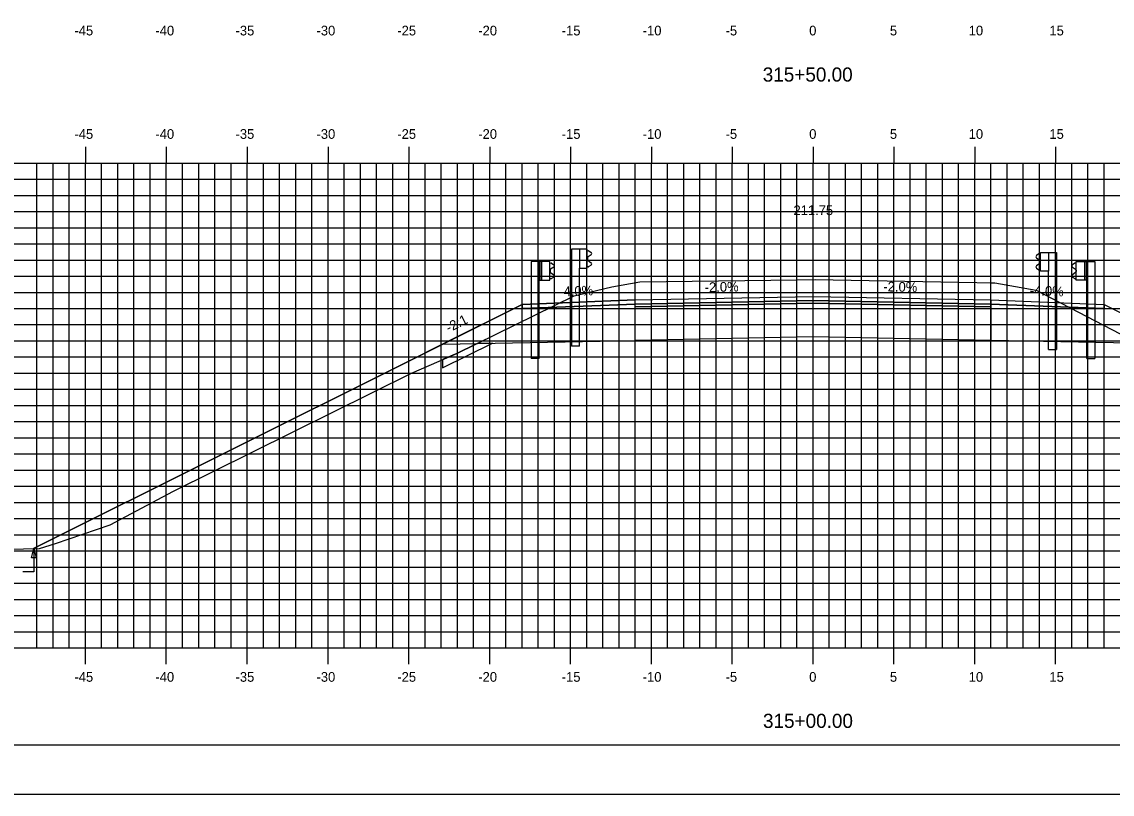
# Model space of a CAD drawing. Extents: x 1138541 to 1138711, y 608981 to 609091.
# Drawn here: x 1138575.5 to 1138642.9, y 608981.3 to 609029.1 of the extents above; entities that cross this region are included whole.
import ezdxf

# ---------------------------------------------------------------- set-up
doc = ezdxf.new("R2010")
doc.units = 0
for name, color, linetype in [('ANNOTATION', 7, 'Continuous'), ('BORDER', 7, 'Continuous'), ('D_Guardrail_Beam_Lt', 7, 'Continuous'), ('D_Guardrail_Beam_Rt', 7, 'Continuous'), ('D_Roadway_Centerline', 7, 'Continuous'), ('D_Roadway_Centerline_Text', 7, 'Continuous'), ('D_Roadway_Edge_Shoulder', 7, 'Continuous'), ('D_Roadway_Edge_TW', 7, 'Continuous'), ('D_Roadway_Pavement', 7, 'Continuous'), ('D_Roadway_SlopeLines', 7, 'Continuous'), ('D_Roadway_SubGrade', 7, 'Continuous'), ('D_Text_Standard', 7, 'Continuous'), ('H_V ANNOTATION', 7, 'Continuous'), ('MAJOR', 7, 'Continuous'), ('MINOR', 7, 'Continuous'), ('PLOT BOUNDARY', 7, 'Continuous'), ('S_Guardrail_Beam', 7, 'Continuous'), ('S_Roadway_Centerline', 7, 'Continuous'), ('SHADING', 7, 'Continuous')]:
    doc.layers.add(name, color=color, linetype=linetype)

msp = doc.modelspace()

# ---------------------------------------------------------------- linework, layer by layer
msp.add_lwpolyline([(1138576.228, 608996.48), (1138599.518, 609008.124), (1138601.518, 609009.124), (1138606.435, 609011.583), (1138606.436, 609011.583), (1138613.436, 609011.863), (1138624.436, 609012.083), (1138635.436, 609011.863), (1138642.436, 609011.583), (1138647.352, 609009.124), (1138649.352, 609008.124), (1138671.518, 608997.041)])
at = {"layer": 'BORDER'}
msp.add_lwpolyline([(1138549.436, 608984.335), (1138709.436, 608984.335), (1138709.436, 609089.335), (1138549.436, 609089.335)], close=True, dxfattribs=at)
at = {"layer": 'D_Guardrail_Beam_Lt'}
for p, q in [((1138607.006, 609014.246), (1138607.006, 609008.246)), ((1138607.477, 609014.246), (1138607.006, 609014.246)), ((1138608.165, 609014.246), (1138607.477, 609014.246)), ((1138607.477, 609014.246), (1138607.477, 609013.079)), ((1138607.54, 609014.246), (1138607.54, 609013.079)), ((1138607.644, 609014.246), (1138607.644, 609013.079)), ((1138608.165, 609013.079), (1138608.165, 609014.246)), ((1138608.165, 609014.163), (1138608.239, 609014.148)), ((1138608.398, 609013.898), (1138608.203, 609013.762)), ((1138608.255, 609014.141), (1138608.398, 609014.041)), ((1138640.616, 609014.141), (1138640.473, 609014.041)), ((1138640.473, 609013.898), (1138640.668, 609013.762)), ((1138640.706, 609014.163), (1138640.632, 609014.148)), ((1138607.477, 609013.079), (1138608.165, 609013.079)), ((1138607.498, 609008.246), (1138607.498, 609013.079)), ((1138608.239, 609013.177), (1138608.165, 609013.163)), ((1138608.169, 609013.698), (1138608.169, 609013.628)), ((1138608.203, 609013.563), (1138608.398, 609013.427)), ((1138608.398, 609013.284), (1138608.255, 609013.184)), ((1138640.668, 609013.563), (1138640.473, 609013.427)), ((1138640.473, 609013.284), (1138640.616, 609013.184)), ((1138640.632, 609013.177), (1138640.706, 609013.163)), ((1138640.702, 609013.698), (1138640.702, 609013.628)), ((1138607.498, 609008.246), (1138607.006, 609008.246))]:
    msp.add_line(p, q, dxfattribs=at)
for centre, major_axis, start_param, end_param in [((1138608.248, 609013.698), (-0.0789, 0), 5.323254, 6.283185), ((1138608.231, 609014.107), (0.0417, 0), 0.959931, 1.376053), ((1138608.348, 609013.97), (0.0877, 0), 5.323254, 7.243116), ((1138640.523, 609013.97), (-0.0877, 0), 5.323254, 7.243116), ((1138640.64, 609014.107), (-0.0417, 0), 4.907132, 5.323254), ((1138640.623, 609013.698), (0.0789, 0), 0, 0.959931), ((1138608.248, 609013.628), (-0.0789, 0), 6.283185, 7.243116), ((1138608.231, 609013.218), (0.0417, 0), 4.907132, 5.323254), ((1138608.348, 609013.356), (0.0877, 0), 5.323254, 7.243116), ((1138640.523, 609013.356), (-0.0877, 0), 5.323254, 7.243116), ((1138640.64, 609013.218), (-0.0417, 0), 0.959931, 1.376053), ((1138640.623, 609013.628), (0.0789, 0), 5.323254, 6.283185)]:
    msp.add_ellipse(centre, major_axis=major_axis, ratio=0.995501, start_param=start_param, end_param=end_param, dxfattribs=at)
at = {"layer": 'D_Guardrail_Beam_Rt'}
for p, q in [((1138640.706, 609014.246), (1138641.394, 609014.246)), ((1138640.706, 609013.079), (1138640.706, 609014.246)), ((1138641.227, 609014.246), (1138641.227, 609013.079)), ((1138641.331, 609014.246), (1138641.331, 609013.079)), ((1138641.394, 609014.246), (1138641.865, 609014.246)), ((1138641.394, 609014.246), (1138641.394, 609013.079)), ((1138641.865, 609014.246), (1138641.865, 609008.246)), ((1138641.394, 609013.079), (1138640.706, 609013.079)), ((1138641.373, 609008.246), (1138641.373, 609013.079)), ((1138641.373, 609008.246), (1138641.865, 609008.246))]:
    msp.add_line(p, q, dxfattribs=at)
at = {"layer": 'D_Roadway_Edge_Shoulder'}
for points in [[(1138613.436, 609011.863), (1138606.436, 609011.583), (1138606.436, 609011.333), (1138613.436, 609011.613)], [(1138635.436, 609011.863), (1138642.436, 609011.583), (1138642.436, 609011.333), (1138635.436, 609011.613)]]:
    msp.add_lwpolyline(points, close=True, dxfattribs=at)
at = {"layer": 'D_Roadway_Edge_TW'}
msp.add_lwpolyline([(1138613.436, 609011.613), (1138613.436, 609011.863), (1138624.436, 609012.083), (1138635.436, 609011.863), (1138635.436, 609011.613), (1138624.436, 609011.833)], close=True, dxfattribs=at)
at = {"layer": 'D_Roadway_Pavement'}
msp.add_lwpolyline([(1138613.436, 609011.446), (1138613.436, 609011.613), (1138624.436, 609011.833), (1138635.436, 609011.613), (1138635.436, 609011.446), (1138624.436, 609011.666)], close=True, dxfattribs=at)
at = {"layer": 'D_Roadway_SlopeLines'}
for points in [[(1138605.065, 609009.862), (1138605.065, 609009.862)], [(1138601.518, 609009.124), (1138599.518, 609008.124)], [(1138601.518, 609008.17), (1138601.518, 609007.67), (1138604.603, 609009.186)], [(1138599.518, 609008.124), (1138576.228, 608996.48)]]:
    msp.add_lwpolyline(points, dxfattribs=at)
at = {"layer": 'D_Roadway_SubGrade'}
msp.add_lwpolyline([(1138606.436, 609011.581), (1138604.436, 609010.581), (1138576.233, 608996.48)], dxfattribs=at)
for points in [[(1138613.436, 609011.446), (1138613.436, 609011.613), (1138606.436, 609011.333), (1138606.436, 609011.583), (1138606.435, 609011.583), (1138601.518, 609009.124), (1138613.436, 609009.363)], [(1138613.436, 609009.363), (1138613.436, 609011.446), (1138624.436, 609011.666), (1138635.436, 609011.446), (1138635.436, 609009.363), (1138624.436, 609009.583)], [(1138635.436, 609011.446), (1138635.436, 609011.613), (1138642.436, 609011.333), (1138642.436, 609011.583), (1138642.436, 609011.583), (1138647.352, 609009.124), (1138635.436, 609009.363)]]:
    msp.add_lwpolyline(points, close=True, dxfattribs=at)
at = {"layer": 'D_Text_Standard'}
msp.add_lwpolyline([(1138576.233, 608996.48), (1138576.239, 608995.034), (1138575.559, 608995.034)], dxfattribs=at)
msp.add_lwpolyline([(1138576.233, 608996.48), (1138576.381, 608995.898), (1138576.09, 608995.897)], close=True, dxfattribs=at)
at = {"layer": 'MAJOR'}
for p, q in [((1138579.436, 609021.337), (1138579.436, 609020.335)), ((1138584.436, 609021.337), (1138584.436, 609020.335)), ((1138589.436, 609021.337), (1138589.436, 609020.335)), ((1138594.436, 609021.337), (1138594.436, 609020.335)), ((1138599.436, 609021.337), (1138599.436, 609020.335)), ((1138604.436, 609021.337), (1138604.436, 609020.335)), ((1138609.436, 609021.337), (1138609.436, 609020.335)), ((1138614.436, 609021.337), (1138614.436, 609020.335)), ((1138619.436, 609021.337), (1138619.436, 609020.335)), ((1138624.436, 609021.337), (1138624.436, 609020.335)), ((1138629.436, 609021.337), (1138629.436, 609020.335)), ((1138634.436, 609021.337), (1138634.436, 609020.335)), ((1138639.436, 609021.337), (1138639.436, 609020.335)), ((1138554.436, 609020.335), (1138694.436, 609020.335)), ((1138554.436, 609020.335), (1138694.436, 609020.335)), ((1138579.436, 608990.335), (1138579.436, 609020.335)), ((1138584.436, 608990.335), (1138584.436, 609020.335)), ((1138589.436, 608990.335), (1138589.436, 609020.335)), ((1138594.436, 608990.335), (1138594.436, 609020.335)), ((1138599.436, 608990.335), (1138599.436, 609020.335)), ((1138604.436, 608990.335), (1138604.436, 609020.335)), ((1138609.436, 608990.335), (1138609.436, 609020.335)), ((1138614.436, 608990.335), (1138614.436, 609020.335)), ((1138619.436, 608990.335), (1138619.436, 609020.335)), ((1138624.436, 608990.335), (1138624.436, 609020.335)), ((1138629.436, 608990.335), (1138629.436, 609020.335)), ((1138634.436, 608990.335), (1138634.436, 609020.335)), ((1138639.436, 608990.335), (1138639.436, 609020.335)), ((1138554.436, 609015.335), (1138694.436, 609015.335)), ((1138554.436, 609010.335), (1138694.436, 609010.335)), ((1138554.436, 609005.335), (1138694.436, 609005.335)), ((1138554.436, 609000.335), (1138694.436, 609000.335)), ((1138554.436, 608995.335), (1138694.436, 608995.335)), ((1138554.436, 608990.335), (1138694.436, 608990.335)), ((1138554.436, 608990.335), (1138694.436, 608990.335)), ((1138579.436, 608989.333), (1138579.436, 608990.335)), ((1138584.436, 608989.333), (1138584.436, 608990.335)), ((1138589.436, 608989.333), (1138589.436, 608990.335)), ((1138594.436, 608989.333), (1138594.436, 608990.335)), ((1138599.436, 608989.333), (1138599.436, 608990.335)), ((1138604.436, 608989.333), (1138604.436, 608990.335)), ((1138609.436, 608989.333), (1138609.436, 608990.335)), ((1138614.436, 608989.333), (1138614.436, 608990.335)), ((1138619.436, 608989.333), (1138619.436, 608990.335)), ((1138624.436, 608989.333), (1138624.436, 608990.335)), ((1138629.436, 608989.333), (1138629.436, 608990.335)), ((1138634.436, 608989.333), (1138634.436, 608990.335)), ((1138639.436, 608989.333), (1138639.436, 608990.335))]:
    msp.add_line(p, q, dxfattribs=at)
at = {"layer": 'MINOR'}
for p, q in [((1138576.436, 608990.335), (1138576.436, 609020.335)), ((1138577.436, 608990.335), (1138577.436, 609020.335)), ((1138578.436, 608990.335), (1138578.436, 609020.335)), ((1138580.436, 608990.335), (1138580.436, 609020.335)), ((1138581.436, 608990.335), (1138581.436, 609020.335)), ((1138582.436, 608990.335), (1138582.436, 609020.335)), ((1138583.436, 608990.335), (1138583.436, 609020.335)), ((1138585.436, 608990.335), (1138585.436, 609020.335)), ((1138586.436, 608990.335), (1138586.436, 609020.335)), ((1138587.436, 608990.335), (1138587.436, 609020.335)), ((1138588.436, 608990.335), (1138588.436, 609020.335)), ((1138590.436, 608990.335), (1138590.436, 609020.335)), ((1138591.436, 608990.335), (1138591.436, 609020.335)), ((1138592.436, 608990.335), (1138592.436, 609020.335)), ((1138593.436, 608990.335), (1138593.436, 609020.335)), ((1138595.436, 608990.335), (1138595.436, 609020.335)), ((1138596.436, 608990.335), (1138596.436, 609020.335)), ((1138597.436, 608990.335), (1138597.436, 609020.335)), ((1138598.436, 608990.335), (1138598.436, 609020.335)), ((1138600.436, 608990.335), (1138600.436, 609020.335)), ((1138601.436, 608990.335), (1138601.436, 609020.335)), ((1138602.436, 608990.335), (1138602.436, 609020.335)), ((1138603.436, 608990.335), (1138603.436, 609020.335)), ((1138605.436, 608990.335), (1138605.436, 609020.335)), ((1138606.436, 608990.335), (1138606.436, 609020.335)), ((1138607.436, 608990.335), (1138607.436, 609020.335)), ((1138608.436, 608990.335), (1138608.436, 609020.335)), ((1138610.436, 608990.335), (1138610.436, 609020.335)), ((1138611.436, 608990.335), (1138611.436, 609020.335)), ((1138612.436, 608990.335), (1138612.436, 609020.335)), ((1138613.436, 608990.335), (1138613.436, 609020.335)), ((1138615.436, 608990.335), (1138615.436, 609020.335)), ((1138616.436, 608990.335), (1138616.436, 609020.335)), ((1138617.436, 608990.335), (1138617.436, 609020.335)), ((1138618.436, 608990.335), (1138618.436, 609020.335)), ((1138620.436, 608990.335), (1138620.436, 609020.335)), ((1138621.436, 608990.335), (1138621.436, 609020.335)), ((1138622.436, 608990.335), (1138622.436, 609020.335)), ((1138623.436, 608990.335), (1138623.436, 609020.335)), ((1138625.436, 608990.335), (1138625.436, 609020.335)), ((1138626.436, 608990.335), (1138626.436, 609020.335)), ((1138627.436, 608990.335), (1138627.436, 609020.335)), ((1138628.436, 608990.335), (1138628.436, 609020.335)), ((1138630.436, 608990.335), (1138630.436, 609020.335)), ((1138631.436, 608990.335), (1138631.436, 609020.335)), ((1138632.436, 608990.335), (1138632.436, 609020.335)), ((1138633.436, 608990.335), (1138633.436, 609020.335)), ((1138635.436, 608990.335), (1138635.436, 609020.335)), ((1138636.436, 608990.335), (1138636.436, 609020.335)), ((1138637.436, 608990.335), (1138637.436, 609020.335)), ((1138638.436, 608990.335), (1138638.436, 609020.335)), ((1138640.436, 608990.335), (1138640.436, 609020.335)), ((1138641.436, 608990.335), (1138641.436, 609020.335)), ((1138642.436, 608990.335), (1138642.436, 609020.335)), ((1138554.436, 609019.335), (1138694.436, 609019.335)), ((1138554.436, 609018.335), (1138694.436, 609018.335)), ((1138554.436, 609017.335), (1138694.436, 609017.335)), ((1138554.436, 609016.335), (1138694.436, 609016.335)), ((1138554.436, 609014.335), (1138694.436, 609014.335)), ((1138554.436, 609013.335), (1138694.436, 609013.335)), ((1138554.436, 609012.335), (1138694.436, 609012.335)), ((1138554.436, 609011.335), (1138694.436, 609011.335)), ((1138554.436, 609009.335), (1138694.436, 609009.335)), ((1138554.436, 609008.335), (1138694.436, 609008.335)), ((1138554.436, 609007.335), (1138694.436, 609007.335)), ((1138554.436, 609006.335), (1138694.436, 609006.335)), ((1138554.436, 609004.335), (1138694.436, 609004.335)), ((1138554.436, 609003.335), (1138694.436, 609003.335)), ((1138554.436, 609002.335), (1138694.436, 609002.335)), ((1138554.436, 609001.335), (1138694.436, 609001.335)), ((1138554.436, 608999.335), (1138694.436, 608999.335)), ((1138554.436, 608998.335), (1138694.436, 608998.335)), ((1138554.436, 608997.335), (1138694.436, 608997.335)), ((1138554.436, 608996.335), (1138694.436, 608996.335)), ((1138554.436, 608994.335), (1138694.436, 608994.335)), ((1138554.436, 608993.335), (1138694.436, 608993.335)), ((1138554.436, 608992.335), (1138694.436, 608992.335)), ((1138554.436, 608991.335), (1138694.436, 608991.335))]:
    msp.add_line(p, q, dxfattribs=at)
at = {"layer": 'PLOT BOUNDARY'}
msp.add_lwpolyline([(1138541.342, 608981.276), (1138711.342, 608981.276), (1138711.342, 609091.276), (1138541.342, 609091.276)], close=True, dxfattribs=at)
at = {"layer": 'S_Guardrail_Beam'}
for p, q in [((1138609.489, 609014.999), (1138609.489, 609008.999)), ((1138609.98, 609014.999), (1138609.489, 609014.999)), ((1138610.47, 609014.999), (1138609.98, 609014.999)), ((1138609.98, 609014.999), (1138609.98, 609013.833)), ((1138610.47, 609013.833), (1138610.47, 609014.999)), ((1138610.47, 609014.926), (1138610.552, 609014.912)), ((1138610.483, 609014.462), (1138610.483, 609014.371)), ((1138610.712, 609014.662), (1138610.517, 609014.526)), ((1138610.569, 609014.905), (1138610.712, 609014.805)), ((1138638.401, 609014.711), (1138638.258, 609014.611)), ((1138638.258, 609014.468), (1138638.453, 609014.332)), ((1138638.5, 609014.732), (1138638.418, 609014.718)), ((1138638.5, 609014.805), (1138638.99, 609014.805)), ((1138638.5, 609013.639), (1138638.5, 609014.805)), ((1138638.99, 609014.805), (1138639.481, 609014.805)), ((1138638.99, 609014.805), (1138638.99, 609013.639)), ((1138639.481, 609014.805), (1138639.481, 609008.805)), ((1138609.98, 609008.999), (1138609.98, 609013.833)), ((1138609.98, 609013.833), (1138610.47, 609013.833)), ((1138610.552, 609013.92), (1138610.47, 609013.906)), ((1138610.517, 609014.306), (1138610.712, 609014.17)), ((1138610.712, 609014.027), (1138610.569, 609013.927)), ((1138638.453, 609014.112), (1138638.258, 609013.976)), ((1138638.258, 609013.833), (1138638.401, 609013.733)), ((1138638.487, 609014.267), (1138638.487, 609014.176)), ((1138638.418, 609013.726), (1138638.5, 609013.711)), ((1138638.99, 609013.639), (1138638.5, 609013.639)), ((1138638.99, 609008.805), (1138638.99, 609013.639)), ((1138609.98, 609008.999), (1138609.489, 609008.999)), ((1138638.99, 609008.805), (1138639.481, 609008.805))]:
    msp.add_line(p, q, dxfattribs=at)
for centre, major_axis, start_param, end_param in [((1138610.562, 609014.462), (-0.0789, 0), 5.323254, 6.283185), ((1138610.545, 609014.871), (0.0417, 0), 0.959931, 1.396263), ((1138610.662, 609014.734), (0.0877, 0), 5.323254, 7.243116), ((1138638.308, 609014.539), (-0.0877, 0), 5.323254, 7.243116), ((1138638.425, 609014.677), (-0.0417, 0), 4.886922, 5.323254), ((1138610.562, 609014.371), (-0.0789, 0), 6.283185, 7.243116), ((1138610.545, 609013.961), (0.0417, 0), 4.886922, 5.323254), ((1138610.662, 609014.098), (0.0877, 0), 5.323254, 7.243116), ((1138638.308, 609013.904), (-0.0877, 0), 5.323254, 7.243116), ((1138638.408, 609014.267), (0.0789, 0), 0, 0.959931), ((1138638.408, 609014.176), (0.0789, 0), 5.323254, 6.283185), ((1138638.425, 609013.767), (-0.0417, 0), 0.959931, 1.396263)]:
    msp.add_ellipse(centre, major_axis=major_axis, ratio=0.995501, start_param=start_param, end_param=end_param, dxfattribs=at)
at = {"layer": 'S_Roadway_Centerline'}
msp.add_lwpolyline([(1138554.436, 608996.093), (1138555.914, 608996.078), (1138556.733, 608996.072), (1138558.742, 608996.121), (1138576.588, 608996.487), (1138577.586, 608996.79), (1138580.96, 608997.947), (1138584.879, 609000.024), (1138599.606, 609007.341), (1138602.407, 609008.555), (1138609.669, 609012.124), (1138611.981, 609012.675), (1138613.716, 609012.981), (1138623.446, 609013.107), (1138624.559, 609013.121), (1138634.558, 609012.938), (1138635.398, 609012.927), (1138635.681, 609012.919), (1138638.229, 609012.472), (1138646.037, 609008.404)], dxfattribs=at)
at = {"layer": 'SHADING'}
msp.add_line((1138604.603, 609009.186), (1138603.651, 609009.167), dxfattribs=at)
for points in [[(1138601.518, 609008.17), (1138601.518, 609007.67), (1138604.603, 609009.186)], [(1138603.651, 609009.167), (1138602.407, 609008.555), (1138601.518, 609008.17)]]:
    msp.add_lwpolyline(points, dxfattribs=at)

# ---------------------------------------------------------------- texts
at = {"layer": 'ANNOTATION'}
for s, rotation, p in [('-4.0%', 2.29061, (1138608.752, 609012.076)), ('-2.0%', 1.14576, (1138617.739, 609012.349)), ('-2.0%', 358.85424, (1138628.779, 609012.396)), ('-4.0%', 357.70939, (1138637.831, 609012.168)), ('-2:1', 26.56505, (1138601.905, 609009.836))]:
    msp.add_text(s, height=0.6, rotation=rotation, dxfattribs=at).set_placement(p)
at = {"layer": 'D_Roadway_Centerline'}
for s, p in [('C', (1138624.43, 609012.083)), ('L', (1138624.436, 609012.075))]:
    msp.add_text(s, height=0.0146, dxfattribs=at).set_placement(p)
at = {"layer": 'D_Roadway_Centerline_Text'}
msp.add_text('211.75', height=0.6, dxfattribs=at).set_placement((1138623.224, 609017.115))
at = {"layer": 'H_V ANNOTATION'}
for s, height, p in [('-45', 0.6, (1138578.753, 609028.235)), ('-40', 0.6, (1138583.761, 609028.235)), ('-35', 0.6, (1138588.716, 609028.235)), ('-30', 0.6, (1138593.724, 609028.235)), ('-25', 0.6, (1138598.721, 609028.235)), ('-20', 0.6, (1138603.729, 609028.235)), ('-15', 0.6, (1138608.892, 609028.235)), ('-10', 0.6, (1138613.9, 609028.235)), ('-5', 0.6, (1138619.026, 609028.235)), ('0', 0.6, (1138624.195, 609028.235)), ('5', 0.6, (1138629.187, 609028.235)), ('10', 0.6, (1138634.061, 609028.235)), ('15', 0.6, (1138639.053, 609028.235)), ('315+50.00', 0.875, (1138621.322, 609025.378)), ('-45', 0.6, (1138578.753, 609021.835)), ('-40', 0.6, (1138583.761, 609021.835)), ('-35', 0.6, (1138588.716, 609021.835)), ('-30', 0.6, (1138593.724, 609021.835)), ('-25', 0.6, (1138598.721, 609021.835)), ('-20', 0.6, (1138603.729, 609021.835)), ('-15', 0.6, (1138608.892, 609021.835)), ('-10', 0.6, (1138613.9, 609021.835)), ('-5', 0.6, (1138619.026, 609021.835)), ('0', 0.6, (1138624.195, 609021.835)), ('5', 0.6, (1138629.187, 609021.835)), ('10', 0.6, (1138634.061, 609021.835)), ('15', 0.6, (1138639.053, 609021.835)), ('-45', 0.6, (1138578.753, 608988.235)), ('-40', 0.6, (1138583.761, 608988.235)), ('-35', 0.6, (1138588.716, 608988.235)), ('-30', 0.6, (1138593.724, 608988.235)), ('-25', 0.6, (1138598.721, 608988.235)), ('-20', 0.6, (1138603.729, 608988.235)), ('-15', 0.6, (1138608.892, 608988.235)), ('-10', 0.6, (1138613.9, 608988.235)), ('-5', 0.6, (1138619.026, 608988.235)), ('0', 0.6, (1138624.195, 608988.235)), ('5', 0.6, (1138629.187, 608988.235)), ('10', 0.6, (1138634.061, 608988.235)), ('15', 0.6, (1138639.053, 608988.235)), ('315+00.00', 0.875, (1138621.338, 608985.378))]:
    msp.add_text(s, height=height, dxfattribs=at).set_placement(p)
at = {"layer": 'S_Roadway_Centerline'}
for s, p in [('C', (1138624.554, 609013.121)), ('L', (1138624.559, 609013.114))]:
    msp.add_text(s, height=0.0146, dxfattribs=at).set_placement(p)

doc.saveas('drawing.dxf')
